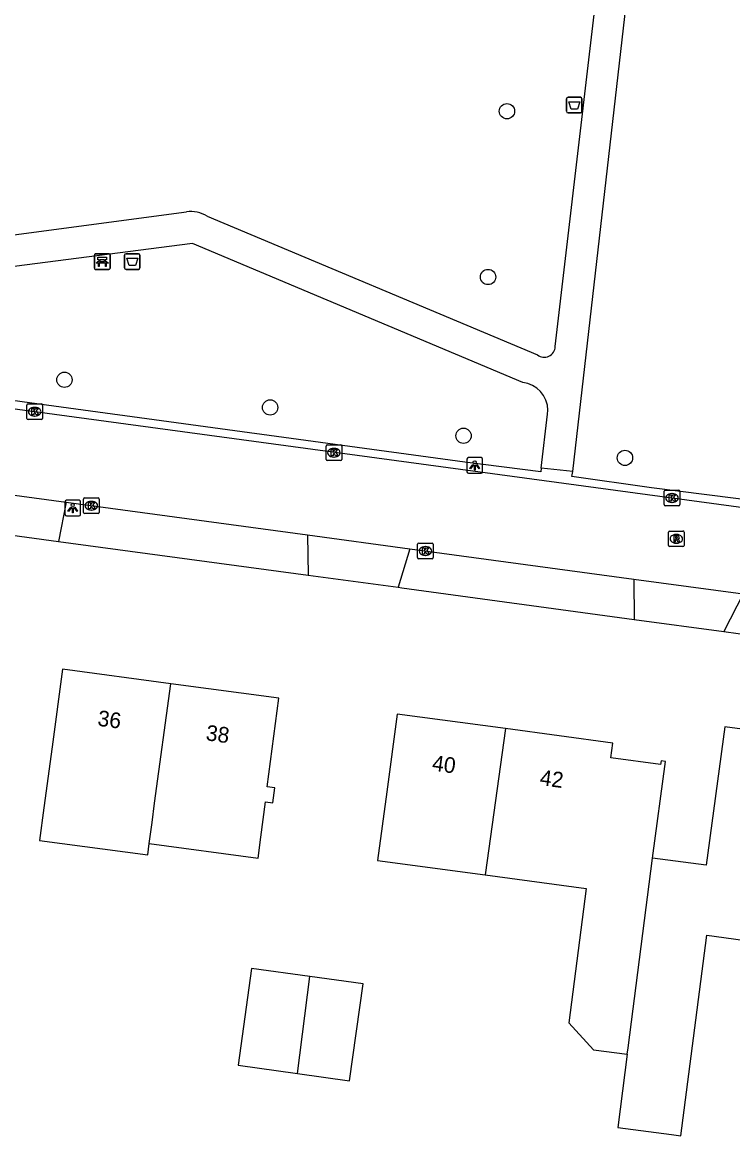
# Model space of a CAD drawing. Extents: x 161696 to 162377, y 380761 to 381673.
# Drawn here: x 162091.1 to 162136.5, y 380836.3 to 380907.4 of the extents above; entities that cross this region are included whole.
import ezdxf

# ---------------------------------------------------------------- set-up
doc = ezdxf.new("R2010")
doc.units = 0
for name, color, linetype in [('IMGEO_Afvalbak', 7, 'Continuous'), ('IMGEO_Bank', 7, 'Continuous'), ('IMGEO_Boom', 7, 'Continuous'), ('IMGEO_Kolk', 7, 'Continuous'), ('IMGEO_Lichtpunt', 7, 'Continuous'), ('IMGEO_Pand', 7, 'Continuous'), ('IMGEO_Pand_nummerreeks', 7, 'Continuous'), ('IMGEO_Rijbaan_lokaal_open', 7, 'Continuous'), ('IMGEO_Rioolput', 7, 'Continuous'), ('IMGEO_Voetpad_gesloten', 7, 'Continuous'), ('IMGEO_Voetpad_open', 7, 'Continuous')]:
    doc.layers.add(name, color=color, linetype=linetype)

msp = doc.modelspace()

# ---------------------------------------------------------------- linework, layer by layer
at = {"layer": 'IMGEO_Afvalbak'}
for p, q in [((162125.853, 380901.694), (162125.853, 380902.494)), ((162125.853, 380902.494), (162125.853, 380901.694)), ((162125.953, 380902.594), (162126.743, 380902.594)), ((162126.743, 380902.594), (162125.953, 380902.594)), ((162126.843, 380902.494), (162126.843, 380901.694)), ((162126.843, 380901.694), (162126.843, 380902.494)), ((162126.743, 380901.594), (162125.953, 380901.594)), ((162125.953, 380901.594), (162126.743, 380901.594)), ((162097.625, 380891.699), (162097.625, 380892.499)), ((162097.625, 380892.499), (162097.625, 380891.699)), ((162097.725, 380892.599), (162098.515, 380892.599)), ((162098.515, 380892.599), (162097.725, 380892.599)), ((162098.615, 380892.499), (162098.615, 380891.699)), ((162098.615, 380891.699), (162098.615, 380892.499)), ((162098.515, 380891.599), (162097.725, 380891.599)), ((162097.725, 380891.599), (162098.515, 380891.599))]:
    msp.add_line(p, q, dxfattribs=at)
for points in [[(162125.996, 380902.308), (162126.7, 380902.308), (162126.551, 380901.838), (162126.145, 380901.838), (162125.996, 380902.308)], [(162097.768, 380892.313), (162098.472, 380892.313), (162098.323, 380891.843), (162097.917, 380891.843), (162097.768, 380892.313)]]:
    msp.add_lwpolyline(points, dxfattribs=at)
for centre, start, end in [((162125.953, 380902.494), 90, 180), ((162125.953, 380902.494), 90, 180), ((162126.743, 380902.494), 0, 90), ((162126.743, 380902.494), 360, 90), ((162125.953, 380901.694), 180, 270), ((162125.953, 380901.694), 180, 270), ((162126.743, 380901.694), 270, 0), ((162126.743, 380901.694), 270, 0), ((162097.725, 380892.499), 90, 180), ((162097.725, 380892.499), 90, 180), ((162098.515, 380892.499), 0, 90), ((162098.515, 380892.499), 360, 90), ((162097.725, 380891.699), 180, 270), ((162097.725, 380891.699), 180, 270), ((162098.515, 380891.699), 270, 0), ((162098.515, 380891.699), 270, 0)]:
    msp.add_arc(centre, 0.1, start, end, dxfattribs=at)
at = {"layer": 'IMGEO_Bank'}
for p, q in [((162095.709, 380891.672), (162095.709, 380892.513)), ((162095.709, 380892.513), (162095.709, 380891.672)), ((162095.784, 380892.597), (162096.625, 380892.597)), ((162096.625, 380892.597), (162095.784, 380892.597)), ((162096.018, 380892.103), (162096.018, 380892.209)), ((162096.062, 380892.209), (162096.062, 380892.103)), ((162096.35, 380892.215), (162096.068, 380892.215)), ((162096.068, 380892.097), (162096.35, 380892.097)), ((162096.356, 380892.103), (162096.356, 380892.209)), ((162096.4, 380892.209), (162096.4, 380892.103)), ((162096.709, 380892.522), (162096.709, 380891.681)), ((162096.709, 380891.681), (162096.709, 380892.522)), ((162096.634, 380891.597), (162095.793, 380891.597)), ((162095.793, 380891.597), (162096.634, 380891.597)), ((162096.406, 380891.995), (162096.013, 380891.995))]:
    msp.add_line(p, q, dxfattribs=at)
for points in [[(162095.956, 380891.995), (162095.814, 380891.995), (162095.926, 380892.097), (162096.012, 380892.097)], [(162096.012, 380892.215), (162095.926, 380892.215), (162095.926, 380892.376), (162096.489, 380892.376), (162096.489, 380892.215), (162096.406, 380892.215)], [(162096.406, 380892.097), (162096.489, 380892.097), (162096.601, 380891.995), (162096.462, 380891.995)], [(162096.006, 380891.988), (162096.006, 380891.781), (162095.963, 380891.781), (162095.963, 380891.988)], [(162096.456, 380891.988), (162096.456, 380891.781), (162096.412, 380891.781), (162096.412, 380891.988)]]:
    msp.add_lwpolyline(points, dxfattribs=at)
for centre, radius, start, end in [((162095.787, 380892.519), 0.0779, 92.4484, 184.28452), ((162095.787, 380892.519), 0.0779, 92.4484, 184.28452), ((162096.011, 380892.208), 0.00671, 2.89567, 87.10433), ((162096.011, 380892.104), 0.00671, 272.89567, 357.10433), ((162096.068, 380892.208), 0.00671, 92.89567, 177.10433), ((162096.068, 380892.104), 0.00671, 182.89567, 267.10433), ((162096.35, 380892.208), 0.00671, 2.89567, 87.10433), ((162096.35, 380892.104), 0.00671, 272.89567, 357.10433), ((162096.407, 380892.208), 0.00671, 92.89567, 177.10433), ((162096.407, 380892.104), 0.00671, 182.89567, 267.10433), ((162096.631, 380892.519), 0.0779, 2.4484, 94.28452), ((162096.631, 380892.519), 0.0779, 2.4484, 94.28452), ((162095.787, 380891.675), 0.0779, 182.4484, 274.28452), ((162095.787, 380891.675), 0.0779, 182.4484, 274.28452), ((162095.956, 380891.988), 0.00671, 2.89567, 87.10433), ((162096.013, 380891.988), 0.00671, 92.89567, 177.10433), ((162096.405, 380891.988), 0.00671, 2.89567, 87.10433), ((162096.462, 380891.988), 0.00671, 92.89567, 177.10433), ((162096.631, 380891.675), 0.0779, 272.4484, 4.28452), ((162096.631, 380891.675), 0.0779, 272.4484, 4.28452)]:
    msp.add_arc(centre, radius, start, end, dxfattribs=at)
at = {"layer": 'IMGEO_Boom'}
for centre in [(162122.054, 380901.7), (162120.846, 380891.111), (162093.792, 380884.546), (162106.93, 380882.779), (162119.28, 380880.971), (162129.591, 380879.557)]:
    msp.add_circle(centre, 0.489, dxfattribs=at)
at = {"layer": 'IMGEO_Kolk'}
for p, q in [((162091.395, 380882.078), (162091.395, 380882.93)), ((162091.47, 380883.004), (162092.322, 380883.004)), ((162091.883, 380882.784), (162091.908, 380882.784)), ((162092.396, 380882.93), (162092.396, 380882.078)), ((162091.906, 380882.224), (162091.881, 380882.224)), ((162092.322, 380882.004), (162091.47, 380882.004)), ((162110.502, 380879.462), (162110.502, 380880.314)), ((162110.577, 380880.388), (162111.429, 380880.388)), ((162110.99, 380880.168), (162111.015, 380880.168)), ((162111.503, 380880.314), (162111.503, 380879.462)), ((162111.429, 380879.388), (162110.577, 380879.388)), ((162111.013, 380879.608), (162110.988, 380879.608)), ((162132.091, 380876.571), (162132.091, 380877.423)), ((162132.166, 380877.497), (162133.018, 380877.497)), ((162132.579, 380877.277), (162132.604, 380877.277)), ((162133.092, 380877.423), (162133.092, 380876.571)), ((162095.011, 380876.077), (162095.011, 380876.929)), ((162095.086, 380877.003), (162095.938, 380877.003)), ((162095.499, 380876.783), (162095.524, 380876.783)), ((162096.012, 380876.929), (162096.012, 380876.077)), ((162133.018, 380876.497), (162132.166, 380876.497)), ((162132.602, 380876.717), (162132.577, 380876.717)), ((162095.938, 380876.003), (162095.086, 380876.003)), ((162095.522, 380876.223), (162095.497, 380876.223)), ((162116.348, 380873.185), (162116.348, 380874.037)), ((162116.423, 380874.111), (162117.275, 380874.111)), ((162116.836, 380873.891), (162116.861, 380873.891)), ((162117.349, 380874.037), (162117.349, 380873.185)), ((162117.275, 380873.111), (162116.423, 380873.111)), ((162116.859, 380873.331), (162116.834, 380873.331))]:
    msp.add_line(p, q, dxfattribs=at)
for points in [[(162091.395, 380882.078), (162091.395, 380882.93)], [(162091.47, 380883.004), (162092.322, 380883.004)], [(162092.396, 380882.93), (162092.396, 380882.078)], [(162091.716, 380882.704), (162091.839, 380882.704), (162091.839, 380882.553), (162091.969, 380882.704), (162092.133, 380882.704), (162091.987, 380882.553), (162092.14, 380882.304), (162091.988, 380882.304), (162091.903, 380882.468), (162091.839, 380882.401), (162091.839, 380882.304), (162091.716, 380882.304), (162091.716, 380882.704)], [(162092.322, 380882.004), (162091.47, 380882.004)], [(162110.502, 380879.462), (162110.502, 380880.314)], [(162110.577, 380880.388), (162111.429, 380880.388)], [(162110.823, 380880.088), (162110.946, 380880.088), (162110.946, 380879.937), (162111.076, 380880.088), (162111.24, 380880.088), (162111.094, 380879.937), (162111.247, 380879.688), (162111.095, 380879.688), (162111.01, 380879.852), (162110.946, 380879.785), (162110.946, 380879.688), (162110.823, 380879.688), (162110.823, 380880.088)], [(162111.503, 380880.314), (162111.503, 380879.462)], [(162111.429, 380879.388), (162110.577, 380879.388)], [(162132.091, 380876.571), (162132.091, 380877.423)], [(162132.166, 380877.497), (162133.018, 380877.497)], [(162132.412, 380877.197), (162132.535, 380877.197), (162132.535, 380877.046), (162132.665, 380877.197), (162132.829, 380877.197), (162132.683, 380877.046), (162132.836, 380876.797), (162132.684, 380876.797), (162132.599, 380876.961), (162132.535, 380876.894), (162132.535, 380876.797), (162132.412, 380876.797), (162132.412, 380877.197)], [(162133.092, 380877.423), (162133.092, 380876.571)], [(162095.011, 380876.077), (162095.011, 380876.929)], [(162095.086, 380877.003), (162095.938, 380877.003)], [(162095.332, 380876.703), (162095.455, 380876.703), (162095.455, 380876.552), (162095.585, 380876.703), (162095.749, 380876.703), (162095.603, 380876.552), (162095.756, 380876.303), (162095.604, 380876.303), (162095.519, 380876.467), (162095.455, 380876.4), (162095.455, 380876.303), (162095.332, 380876.303), (162095.332, 380876.703)], [(162096.012, 380876.929), (162096.012, 380876.077)], [(162133.018, 380876.497), (162132.166, 380876.497)], [(162095.938, 380876.003), (162095.086, 380876.003)], [(162116.348, 380873.185), (162116.348, 380874.037)], [(162116.423, 380874.111), (162117.275, 380874.111)], [(162116.669, 380873.811), (162116.792, 380873.811), (162116.792, 380873.66), (162116.922, 380873.811), (162117.086, 380873.811), (162116.94, 380873.66), (162117.093, 380873.411), (162116.941, 380873.411), (162116.856, 380873.575), (162116.792, 380873.508), (162116.792, 380873.411), (162116.669, 380873.411), (162116.669, 380873.811)], [(162117.349, 380874.037), (162117.349, 380873.185)], [(162117.275, 380873.111), (162116.423, 380873.111)]]:
    msp.add_lwpolyline(points, dxfattribs=at)
for centre, start, end in [((162091.472, 380882.928), 91.55205, 178.44795), ((162091.472, 380882.928), 91.55205, 178.44795), ((162092.32, 380882.928), 1.55205, 88.44795), ((162092.32, 380882.928), 1.55205, 88.44795), ((162091.472, 380882.08), 181.55205, 268.44795), ((162091.472, 380882.08), 181.55205, 268.44795), ((162092.32, 380882.08), 271.55205, 358.44795), ((162092.32, 380882.08), 271.55205, 358.44795), ((162110.579, 380880.312), 91.55205, 178.44795), ((162110.579, 380880.312), 91.55205, 178.44795), ((162111.427, 380880.312), 1.55205, 88.44795), ((162111.427, 380880.312), 1.55205, 88.44795), ((162110.579, 380879.464), 181.55205, 268.44795), ((162110.579, 380879.464), 181.55205, 268.44795), ((162111.427, 380879.464), 271.55205, 358.44795), ((162111.427, 380879.464), 271.55205, 358.44795), ((162132.168, 380877.421), 91.55205, 178.44795), ((162132.168, 380877.421), 91.55205, 178.44795), ((162133.016, 380877.421), 1.55205, 88.44795), ((162133.016, 380877.421), 1.55205, 88.44795), ((162095.088, 380876.927), 91.55205, 178.44795), ((162095.088, 380876.927), 91.55205, 178.44795), ((162095.936, 380876.927), 1.55205, 88.44795), ((162095.936, 380876.927), 1.55205, 88.44795), ((162132.168, 380876.573), 181.55205, 268.44795), ((162132.168, 380876.573), 181.55205, 268.44795), ((162133.016, 380876.573), 271.55205, 358.44795), ((162133.016, 380876.573), 271.55205, 358.44795), ((162095.088, 380876.079), 181.55205, 268.44795), ((162095.088, 380876.079), 181.55205, 268.44795), ((162095.936, 380876.079), 271.55205, 358.44795), ((162095.936, 380876.079), 271.55205, 358.44795), ((162116.425, 380874.035), 91.55205, 178.44795), ((162116.425, 380874.035), 91.55205, 178.44795), ((162117.273, 380874.035), 1.55205, 88.44795), ((162117.273, 380874.035), 1.55205, 88.44795), ((162116.425, 380873.187), 181.55205, 268.44795), ((162116.425, 380873.187), 181.55205, 268.44795), ((162117.273, 380873.187), 271.55205, 358.44795), ((162117.273, 380873.187), 271.55205, 358.44795)]:
    msp.add_arc(centre, 0.0765, start, end, dxfattribs=at)
for centre, major_axis, ratio, start_param, end_param in [((162091.882, 380882.504), (-0.387, 0.002), 0.722429, 4.712389, 7.853982), ((162091.907, 380882.504), (-0.39, 0.002), 0.717154, 1.570796, 4.712389), ((162110.989, 380879.888), (-0.387, 0.002), 0.722429, 4.712389, 7.853982), ((162111.014, 380879.888), (-0.39, 0.002), 0.717154, 1.570796, 4.712389), ((162132.578, 380876.997), (-0.387, 0.002), 0.722429, 4.712389, 7.853982), ((162132.603, 380876.997), (-0.39, 0.002), 0.717154, 1.570796, 4.712389), ((162095.498, 380876.503), (-0.387, 0.002), 0.722429, 4.712389, 7.853982), ((162095.523, 380876.503), (-0.39, 0.002), 0.717154, 1.570796, 4.712389), ((162116.835, 380873.611), (-0.387, 0.002), 0.722429, 4.712389, 7.853982), ((162116.86, 380873.611), (-0.39, 0.002), 0.717154, 1.570796, 4.712389)]:
    msp.add_ellipse(centre, major_axis=major_axis, ratio=ratio, start_param=start_param, end_param=end_param, dxfattribs=at)
at = {"layer": 'IMGEO_Lichtpunt'}
for p, q in [((162119.499, 380879.479), (162119.499, 380878.672)), ((162119.499, 380879.479), (162119.499, 380878.672)), ((162120.401, 380879.574), (162119.593, 380879.574)), ((162120.401, 380879.574), (162119.593, 380879.574)), ((162120.495, 380878.672), (162120.495, 380879.479)), ((162120.495, 380878.672), (162120.495, 380879.479)), ((162119.593, 380878.578), (162120.401, 380878.578)), ((162119.593, 380878.578), (162120.401, 380878.578)), ((162093.826, 380876.756), (162093.826, 380875.949)), ((162093.826, 380876.756), (162093.826, 380875.949)), ((162094.728, 380876.851), (162093.92, 380876.851)), ((162094.728, 380876.851), (162093.92, 380876.851)), ((162094.822, 380875.949), (162094.822, 380876.756)), ((162094.822, 380875.949), (162094.822, 380876.756)), ((162093.92, 380875.855), (162094.728, 380875.855)), ((162093.92, 380875.855), (162094.728, 380875.855))]:
    msp.add_line(p, q, dxfattribs=at)
for points in [[(162119.873, 380879.143), (162119.912, 380879.115), (162119.724, 380878.853), (162119.686, 380878.88), (162119.873, 380879.143)], [(162119.975, 380879.095), (162120.022, 380879.095), (162120.022, 380878.773), (162119.975, 380878.773), (162119.975, 380879.095)], [(162120.085, 380879.115), (162120.123, 380879.142), (162120.31, 380878.88), (162120.271, 380878.852), (162120.085, 380879.115)], [(162094.2, 380876.42), (162094.239, 380876.392), (162094.051, 380876.13), (162094.013, 380876.157), (162094.2, 380876.42)], [(162094.302, 380876.372), (162094.349, 380876.372), (162094.349, 380876.05), (162094.302, 380876.05), (162094.302, 380876.372)], [(162094.412, 380876.392), (162094.45, 380876.419), (162094.637, 380876.157), (162094.598, 380876.129), (162094.412, 380876.392)]]:
    msp.add_lwpolyline(points, dxfattribs=at)
for centre in [(162119.998, 380879.277), (162094.325, 380876.554)]:
    msp.add_circle(centre, 0.0994, dxfattribs=at)
for centre, start, end in [((162119.593, 380879.479), 90, 180), ((162119.593, 380879.479), 90, 180), ((162120.401, 380879.479), 0, 90), ((162120.401, 380879.479), 0, 90), ((162119.593, 380878.672), 180, 270), ((162119.593, 380878.672), 180, 270), ((162120.401, 380878.672), 270, 0), ((162120.401, 380878.672), 270, 360), ((162093.92, 380876.756), 90, 180), ((162093.92, 380876.756), 90, 180), ((162094.728, 380876.756), 0, 90), ((162094.728, 380876.756), 0, 90), ((162093.92, 380875.949), 180, 270), ((162093.92, 380875.949), 180, 270), ((162094.728, 380875.949), 270, 0), ((162094.728, 380875.949), 270, 360)]:
    msp.add_arc(centre, 0.0946, start, end, dxfattribs=at)
at = {"layer": 'IMGEO_Pand'}
for points in [[(162100.58, 380865.132), (162093.672, 380866.061), (162093.006, 380861.106), (162092.481, 380857.203), (162092.202, 380855.129), (162099.109, 380854.2), (162099.208, 380854.937)], [(162099.208, 380854.937), (162099.388, 380856.274), (162099.555, 380857.512), (162100.58, 380865.132)], [(162099.208, 380854.937), (162106.155, 380854.002), (162106.335, 380855.339), (162106.637, 380857.582), (162107.106, 380857.519), (162107.236, 380858.482), (162106.731, 380858.55), (162107.491, 380864.202), (162100.58, 380865.132)], [(162121.965, 380862.265), (162115.042, 380863.196), (162114.374, 380858.226), (162113.785, 380853.851), (162120.666, 380852.926)], [(162121.965, 380862.265), (162120.666, 380852.926)], [(162131.356, 380853.995), (162132.182, 380860.174), (162131.895, 380860.213), (162131.862, 380859.965), (162128.69, 380860.392), (162128.818, 380861.343), (162121.965, 380862.265)], [(162142.945, 380861.442), (162135.975, 380862.379), (162134.785, 380853.534), (162131.356, 380853.995)], [(162129.737, 380841.469), (162129.791, 380841.88), (162131.356, 380853.995)], [(162120.666, 380852.926), (162127.118, 380852.058), (162125.996, 380843.474), (162127.576, 380841.751), (162129.737, 380841.469)], [(162129.737, 380841.469), (162129.126, 380836.789), (162132.561, 380836.34), (162133.152, 380836.263), (162133.817, 380841.354), (162134.824, 380849.064), (162141.165, 380848.211), (162141.207, 380848.523)], [(162109.468, 380846.432), (162105.75, 380846.951), (162104.888, 380840.771), (162108.68, 380840.242)], [(162108.68, 380840.242), (162109.468, 380846.432)], [(162108.68, 380840.242), (162112, 380839.779), (162112.862, 380845.959), (162109.468, 380846.432)]]:
    msp.add_lwpolyline(points, dxfattribs=at)
at = {"layer": 'IMGEO_Rijbaan_lokaal_open'}
for points in [[(162170.61, 380871.806), (162163.55, 380872.779), (162154.919, 380873.969), (162091.896, 380882.503), (162058.39, 380887.022), (162030.224, 380890.812), (162015.929, 380892.766), (162007.423, 380893.947), (162000, 380894.945), (161985.053, 380896.954), (161959.395, 380900.457), (161942.172, 380902.766), (161924.816, 380905.114), (161917.572, 380906.053), (161914.984, 380906.421)], [(162086.972, 380877.66), (162093.903, 380876.722)], [(162093.903, 380876.722), (162109.31, 380874.634)], [(162109.31, 380874.634), (162115.858, 380873.747)], [(162115.858, 380873.747), (162130.159, 380871.815)], [(162130.159, 380871.815), (162137.142, 380870.872)]]:
    msp.add_lwpolyline(points, dxfattribs=at)
at = {"layer": 'IMGEO_Rioolput'}
for p, q in [((162132.367, 380873.962), (162132.367, 380874.814)), ((162132.442, 380874.888), (162133.294, 380874.888)), ((162132.855, 380874.668), (162132.88, 380874.668)), ((162133.368, 380874.814), (162133.368, 380873.962)), ((162133.294, 380873.888), (162132.442, 380873.888)), ((162132.878, 380874.108), (162132.853, 380874.108))]:
    msp.add_line(p, q, dxfattribs=at)
for points in [[(162132.367, 380873.962), (162132.367, 380874.814)], [(162132.442, 380874.888), (162133.294, 380874.888)], [(162132.956, 380874.586), (162132.704, 380874.588), (162132.704, 380874.188)], [(162132.704, 380874.188), (162132.828, 380874.188), (162132.828, 380874.35), (162132.839, 380874.35)], [(162132.882, 380874.507), (162132.828, 380874.507), (162132.828, 380874.426)], [(162132.828, 380874.426), (162132.88, 380874.426)], [(162132.886, 380874.321), (162132.957, 380874.188), (162133.097, 380874.188), (162133.032, 380874.314)], [(162133.368, 380874.814), (162133.368, 380873.962)], [(162133.294, 380873.888), (162132.442, 380873.888)]]:
    msp.add_lwpolyline(points, dxfattribs=at)
for centre, radius, start, end in [((162132.444, 380874.812), 0.0765, 91.55205, 178.44795), ((162132.444, 380874.812), 0.0765, 91.55205, 178.44795), ((162132.838, 380874.297), 0.0533, 26.02933, 88.69889), ((162132.864, 380874.615), 0.19, 274.7715, 282.96867), ((162132.888, 380874.411), 0.0964, 77.00612, 93.18647), ((162132.902, 380874.468), 0.0378, 276.66336, 79.67722), ((162132.955, 380874.476), 0.109, 350.36119, 89.41601), ((162132.953, 380874.476), 0.112, 277.58423, 350.98172), ((162132.937, 380874.261), 0.108, 29.51342, 73.79051), ((162133.292, 380874.812), 0.0765, 1.55205, 88.44795), ((162133.292, 380874.812), 0.0765, 1.55205, 88.44795), ((162132.444, 380873.964), 0.0765, 181.55205, 268.44795), ((162132.444, 380873.964), 0.0765, 181.55205, 268.44795), ((162133.292, 380873.964), 0.0765, 271.55205, 358.44795), ((162133.292, 380873.964), 0.0765, 271.55205, 358.44795)]:
    msp.add_arc(centre, radius, start, end, dxfattribs=at)
for centre, major_axis, ratio, start_param, end_param in [((162132.854, 380874.388), (-0.387, 0.002), 0.722429, 4.712389, 7.853982), ((162132.879, 380874.388), (-0.39, 0.002), 0.717154, 1.570796, 4.712389)]:
    msp.add_ellipse(centre, major_axis=major_axis, ratio=ratio, start_param=start_param, end_param=end_param, dxfattribs=at)
at = {"layer": 'IMGEO_Voetpad_gesloten'}
for points in [[(162125.143, 380886.667), (162128.726, 380917.341)], [(162126.267, 380878.692), (162130.514, 380915.971)], [(162088.314, 380893.507), (162101.599, 380895.276)], [(162102.906, 380895.005), (162123.998, 380886.134)], [(162123.059, 380884.375), (162101.969, 380893.255), (162087.912, 380891.433)], [(162124.242, 380878.904), (162124.64, 380882.344), (162124.67, 380882.601)], [(162126.267, 380878.692), (162124.242, 380878.904)]]:
    msp.add_lwpolyline(points, dxfattribs=at)
for centre, radius, start, end in [((162101.859, 380893.244), 2.048, 59.26876, 97.30322), ((162124.434, 380886.695), 0.71, 232.16636, 357.75781), ((162122.867, 380882.582), 1.803, 0.60738, 83.87888)]:
    msp.add_arc(centre, radius, start, end, dxfattribs=at)
at = {"layer": 'IMGEO_Voetpad_open'}
for points in [[(162124.242, 380878.904), (162124.228, 380878.67), (162119.354, 380879.284), (162092.654, 380882.935), (162060.512, 380887.33), (162052.807, 380888.348)], [(162172.879, 380872.08), (162163.634, 380873.357), (162156.037, 380874.407), (162145.584, 380875.831), (162131.289, 380877.654), (162126.199, 380878.375), (162126.267, 380878.692)], [(162093.903, 380876.722), (162093.416, 380874.228)], [(162087.325, 380875.053), (162093.416, 380874.228)], [(162109.31, 380874.634), (162109.365, 380872.07)], [(162093.416, 380874.228), (162109.365, 380872.07)], [(162115.858, 380873.747), (162115.097, 380871.294)], [(162109.365, 380872.07), (162115.097, 380871.294)], [(162130.159, 380871.815), (162130.186, 380869.241)], [(162115.097, 380871.294), (162115.336, 380871.262), (162130.186, 380869.241)], [(162137.142, 380870.872), (162135.902, 380868.463)], [(162130.186, 380869.241), (162135.902, 380868.463)], [(162135.902, 380868.463), (162136.812, 380868.339), (162152.746, 380866.172), (162158.831, 380865.336), (162162.074, 380861.396)]]:
    msp.add_lwpolyline(points, dxfattribs=at)

# ---------------------------------------------------------------- texts
at = {"layer": 'IMGEO_Pand_nummerreeks'}
for s, rotation, p in [('36', 352.33955, (162095.87, 380862.456)), ('38', 352.33955, (162102.783, 380861.527)), ('40', 352.33916, (162117.232, 380859.593)), ('42', 352.33916, (162124.114, 380858.666))]:
    msp.add_text(s, height=1, rotation=rotation, dxfattribs=at).set_placement(p)

doc.saveas('drawing.dxf')
